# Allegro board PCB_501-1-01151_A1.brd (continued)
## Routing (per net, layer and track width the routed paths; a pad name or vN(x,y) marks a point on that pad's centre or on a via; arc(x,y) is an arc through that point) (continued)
PHYB_RXD0: length 15.5
  TOP w0.142: v1(49.78,30.51) 49.78,31.08 49.66,31.2 49.12,31.2 49,31.33 49,31.5 49.12,31.63 49.83,31.63 49.96,31.75 49.96,31.93 49.83,32.06 49.21,32.06 49.09,32.18 49.09,32.36 49.21,32.48 49.66,32.48 49.78,32.61 49.78,32.88 49.97,33.06 50.26,33.06 50.39,33.18 50.39,33.53 50.51,33.66 50.69,33.66 50.81,33.53 50.81,33.18 50.94,33.06 51.37,33.06 51.54,33.22 51.54,33.9 51.37,34.07 50.36,34.07 50.26,34.17 50.26,34.51 50.43,34.69 50.82,34.69 52.85,36.72 53.53,36.72 U6.C17
  BOTTOM w0.142: R122.2 v1(49.78,30.51)
PHYB_RXD1: length 15.7
  TOP w0.142: U6.C16 v1(54.18,36.57)
  BOTTOM w0.142: v1(54.18,36.57) 54.18,35.21 52.95,33.97 52.74,33.97 52.62,34.1 52.62,35.21 52.49,35.33 52.32,35.33 52.19,35.21 52.19,34.1 52.07,33.97 51.62,33.97 51.49,33.85 51.49,33.33 51.37,33.2 51.19,33.2 51.07,33.33 51.07,34.11 50.94,34.24 50.52,34.24 50.38,34.1 50.38,32.72 50.34,32.68 50.34,31.33 50.23,31.22 49.46,31.22 49.28,31.03 49.28,30.5 R123.2
PHYB_RXER: length 17.5
  TOP w0.142: U6.D16 v1(54.18,37.37)
  BOTTOM w0.142: R125.2 R115.1 51.42,30.84 51.56,30.99 51.56,32.64 52.01,33.09 52.56,33.09 53.22,33.75 53.69,33.75 53.9,33.54 53.9,31.76 54.1,31.56 54.4,31.56 54.58,31.75 54.58,32.63 54.71,32.75 54.99,32.75 55.11,32.88 55.11,33.06 54.99,33.18 54.71,33.18 54.58,33.31 54.58,33.48 54.71,33.61 54.99,33.61 55.11,33.73 55.11,33.91 54.99,34.03 54.71,34.03 54.58,34.16 54.58,34.34 54.71,34.46 54.99,34.46 55.11,34.59 55.11,34.76 54.99,34.89 54.71,34.89 54.58,35.01 54.58,36.97 v1(54.18,37.37)
PHYB_TX_EN: length 5.6
  BOTTOM w0.142: R85.1 44.2,31.98 44.2,28.69 44.72,28.17 U10.49
PHYB_TXD0: length 5.4
  BOTTOM w0.142: U10.48 44.22,28.18 43.56,28.84 R83.1
PHYB_TXD1: length 5.7
  BOTTOM w0.142: R84.1 42.42,29.49 43.72,28.19 U10.47
PMIC_AC_DET: length 6.8
  TOP w0.142: R10.1 R15.2 51.8,61.7 50.5,60.4 48.37,60.4 47.9,59.93 U1.9
PMIC_CC: length 1.2
  TOP w0.142: 40.17,61.73 40.76,61.13 U1.25
PMIC_GPIO1: length 87.4
  TOP w0.142: v1(28.7,44.07) 27.79,44.07 26.6,42.87 26.6,38.23 27.87,36.96 31.5,36.96 32,37.47 R31.2 ; U1.11 48,60.73 48.17,60.9 49.04,60.9 51.05,62.91 R28.1 51.54,65.51 51.68,65.65 51.68,68.46 51.81,68.59 51.81,71.51 49.4,73.91 41.4,73.91 38.8,71.31 34.35,71.31 30.99,67.94 v1(22.99,67.94)
  BOTTOM w0.142: v1(22.99,67.94) 22.99,64.13 25.15,61.98 25.15,56.05 28.07,53.12 28.07,49.53 27.18,48.64 27.18,45.59 v1(28.7,44.07)
PMIC_I2C1_SCL: length 111
  TOP w0.142: U6.G17 53.14,40.18 52.51,39.56 52.51,39 51.76,38.24 51.76,38.23 51.39,37.86 51.39,36.77 47.44,32.82 40.08,32.82 38.35,31.09 30.32,31.09 25.37,36.04 25.37,43.91 26.89,45.43 26.89,47.28 26,48.16 24.61,48.16 23.81,48.96 23.05,48.96 v1(22.73,48.64) ; v1(49.02,56.39) 47.88,57.53 U1.3 ; R580.2 R875.1 16.53,68.6 15.88,67.95 15.88,62.77 16.41,62.23 17.27,62.23 18.16,61.34 18.16,57.79 18.67,57.28 22.99,57.28 v1(23.24,57.53)
  L3_SIG1 w0.142: v1(23.24,57.53) 34,57.53 34.73,56.8 44.9,56.8 45.13,57.02 48.39,57.02 v1(49.02,56.39)
  BOTTOM w0.142: v1(23.24,57.53) 21.46,55.75 21.46,52.2 22.99,50.67 22.99,49.35 22.73,49.09 v1(22.73,48.64)
PMIC_I2C1_SDA: length 99.5
  TOP w0.142: v1(24.33,56.97) 23.82,56.97 23.74,56.9 18.04,56.9 17.72,56.58 17.72,55.57 17.51,55.35 R876.2 R581.2 ; v1(23.62,48.26) 24.06,47.82 25.71,47.82 26.54,46.99 26.54,45.57 25.03,44.06 25.03,35.9 30.18,30.74 38.49,30.74 40.22,32.47 47.58,32.47 47.94,32.82 47.94,32.82 51.73,36.62 51.73,37.71 52.1,38.08 52.1,38.1 52.86,38.86 52.86,39.41 53.18,39.73 54.15,39.73 U6.G16 ; U1.2 47.65,57.13 48.39,56.39 v1(48.39,56.13)
  L3_SIG1 w0.142: v1(48.39,56.13) 47.62,55.37 42.8,55.37 42.16,54.74 39.12,54.74 38.1,55.75 34.04,55.75 32.82,56.97 v1(24.33,56.97)
  BOTTOM w0.142: v1(24.33,56.97) 23.82,56.97 21.81,54.96 21.81,52.34 23.37,50.78 23.37,48.97 23.62,48.71 v1(23.62,48.26)
PMIC_IN_CC#: length 2.6
  TOP w0.142: U1.18 44.27,62.74 v1(44.29,62.76)
  BOTTOM w0.142: v1(44.29,62.76) 43.01,62.76 R766.1
PMIC_INT#: length 85.3
  TOP w0.142: v1(46,53.93) 46,54.42 45.07,55.35 U1.45 ; U6.F5 v1(63.81,38.97)
  L4_SIG2 w0.142: v1(63.81,38.97) 63.41,38.57 52.79,38.57 52.45,38.22 42.74,38.22 42.62,38.1 v1(42.16,38.1) ; v1(25.27,49.78) 29.09,53.61 45.68,53.61 v1(46,53.93)
  BOTTOM w0.142: v1(25.27,49.78) 24.89,49.4 24.89,47.95 25.4,47.45 25.4,40.13 26.8,38.73 26.8,36.18 29.17,33.81 31.26,33.81 31.33,33.74 32.21,33.74 32.27,33.81 33.17,33.81 37.85,38.48 38.86,38.48 41.27,40.89 42.42,40.89 42.93,40.39 R25.1 42.18,38.12 v1(42.16,38.1)
PMIC_PB: length 224.8
  TOP w0.142: U6.J15 v1(54.98,41.37) ; v1(93.22,72.52) 92.2,71.5 92.2,68.83 92.46,68.58 R842.1 ; v1(15.66,51.38) 15.98,51.7 15.98,52.72 15.6,53.11 R841.2
  L3_SIG1 w0.142: v1(54.98,41.37) 52.88,41.37 52.39,41.86 50.99,41.86 50.43,41.31 42.02,41.31 40.57,39.86 40.57,38.81 38.3,36.54 35.91,36.54 33.43,34.06 25.25,34.06 24.77,34.54 12.32,34.54 v1(11.3,33.53) ; v1(15.66,51.38) 15.66,51.84 15.43,52.07 9.94,52.07 7.82,54.2 7.82,73.06 12.54,77.78 21.14,77.78 35.94,92.58 87.38,92.58 93.22,86.74 v1(93.22,72.52)
  BOTTOM w0.142: v1(11.3,33.53) 11.3,34.29 5.62,39.97 5.62,49.05 6.1,49.53 7.87,49.53 8.46,50.12 10.67,50.12 11.25,50.7 12.04,50.7 12.45,50.29 14.57,50.29 v1(15.66,51.38)
PMIC_PB_B: length 75.2
  TOP w0.142: SW2.2 95.17,71.42 94.87,71.12 R20.1 R843.2 R842.2 v1(95.5,68.58) ; v1(46.2,52.92) 45.26,53.86 45.26,54.82 44.83,55.25 44.77,55.25 44.67,55.35 U1.44
  L4_SIG2 w0.142: v1(46.2,52.92) 46.8,52.92 50.12,56.24 51.16,56.24 55.28,60.36 63.97,60.36 64.94,59.39 74.38,59.39 74.94,59.95 75.93,59.95 76.19,59.69 88.75,59.69 90.79,57.66 92.54,57.66 92.86,57.98 93.18,57.98 94.23,59.03 94.23,67.31 v1(95.5,68.58)
PMIC_PFI: length 5.3
  TOP w0.142: U1.16 45.07,62.51 44.94,62.64 44.94,63.42 44.82,63.53 v1(44.82,63.93)
  BOTTOM w0.142: R24.2 R22.1 45.68,64.79 v1(44.82,63.93)
PMIC_PFO#: length 9.5
  TOP w0.142: R859.2 R860.2 51.69,65 51.69,63.12 49.22,60.65 48.27,60.65 47.95,60.33 U1.10
PMIC_PGOOD: length 24.4
  TOP w0.142: R769.1 53.32,60.71 53.47,60.85 v1(53.47,60.96) 53.85,60.96 54.1,60.71 U2.2 55.23,60.71 55.37,60.85 55.37,62.06 55.98,62.67 55.98,63.22 TP40.1 56.77,64.74 57.02,64.99 R23.2
  BOTTOM w0.142: R768.1 44.45,66.93 44.7,67.18 48.35,67.18 48.9,66.63 48.9,64.9 49.66,64.13 53.59,64.13 54.31,63.42 54.31,61.8 v1(53.47,60.96)
PMIC_PWR_EN: length 144.4
  TOP w0.142: U1.46 45.47,55.35 46.52,54.3 46.52,53.91 46.53,53.89 v1(46.53,53.49) ; v1(58.95,71.99) 55.17,71.99 54.61,71.43 54.61,69.98 55.12,69.47 55.12,67.31 54.97,67.16 R88.2 R19.1 ; R859.1 R19.1 ; R19.1 R18.1 ; v1(86.41,77.02) 86.41,77.65 87.88,79.12 95.53,79.12 96.04,78.61 TP34.1 96.77,80.05 94.02,82.8 R833.1 92.19,82.58 U26.1
  L3_SIG1 w0.142: v1(86.41,77.02) 85.07,77.02 84.49,77.6 59.87,77.6 58.29,76.02 58.29,72.64 58.43,72.5 58.44,72.5 v1(58.95,71.99)
  L4_SIG2 w0.142: v1(46.53,53.49) 46.85,53.81 47.12,53.81 49.89,56.58 50.36,56.58 51.01,56.58 55.14,60.71 64.39,60.71 65.36,59.74 73.84,59.74 75.06,60.96 80.77,60.96 81.62,60.11 90,60.11 91.79,58.32 93.03,58.32 93.85,59.14 93.85,71.21 93.05,72.01 91.95,72.01 86.94,77.02 v1(86.41,77.02)
PMIC_PWR_EN_R: length 30.7
  TOP w0.142: R88.1 54.48,68.96 v1(54.61,69.09) ; U6.T9 59.82,47.76 59.82,48.63 59.11,49.33 59.11,54.18 60.66,55.72 61.42,55.72 61.63,55.93 61.63,58.41 60.07,59.97 60.07,62.1 57.69,64.49 57.69,68.55 55.88,70.36 v1(55.09,70.36)
  BOTTOM w0.142: v1(55.09,70.36) 55.09,69.57 v1(54.61,69.09)
PMIC_STBY_REQ: length 1.7
  BOTTOM w0.142: Q41.1 34.69,61.36 34.67,61.34 R765.2
PMIC_WAKE#: length 32.3
  TOP w0.142: U6.R10 v1(58.98,47) ; R26.2 v1(41.91,49.08) 42.29,49.46 42.29,54 43.01,54.71 43.01,55.29 43.07,55.35 U1.40
  L4_SIG2 w0.142: v1(58.98,47) 58.98,49 58.3,49.69 58.3,51.3 56.27,53.33 51.59,53.33 48.76,50.51 43.34,50.51 v1(41.91,49.08)
POR_B: length 142.7
  TOP w0.142: v1(90.17,81.53) 90.17,86.87 91.06,87.76 91.06,89.66 91.95,90.55 93.98,90.55 94.38,90.16 U27.1 ; v1(45.72,79.25) 42.93,79.25 41.02,77.34 41.02,74.8 38.48,72.26 33.66,72.26 29.84,68.45 19.32,68.45 18.56,69.22 15.75,69.22 15.11,68.58 TP35.1 14.38,67.82 14,68.2 D26.2 ; U6.P8 v1(61.41,46.2) ; v1(57.79,57.02) 58.17,57.4 R803.1
  L3_SIG1 w0.142: v1(90.17,81.53) 79.29,81.53 79.19,81.44 68.96,81.44 66.14,78.61 60.34,78.61 59.89,78.16 57.33,78.16 54.74,75.56 v1(52.2,75.56)
  L4_SIG2 w0.142: v1(45.72,79.25) 48.97,79.25 52.2,76.02 v1(52.2,75.56) ; v1(61.41,46.2) 61.81,45.79 63.17,45.79 63.41,46.03 63.41,46.78 63.39,46.8 63.39,47.14 63.41,47.16 63.41,51.29 62.77,51.93 62.77,52.59 58.33,57.02 v1(57.79,57.02)
  BOTTOM w0.142: v1(57.79,57.02) 57.79,57.64 54.65,60.77 54.65,63.57 54.01,64.21 54.01,66.71 54.99,67.69 54.99,68.31 55.63,68.94 55.63,70.61 54.36,71.88 54.36,73.86 52.65,75.56 v1(52.2,75.56)
PRTDIS_M6: length 5.8
  TOP w0.142: U14.53 76.17,67.59 76.96,66.8 76.96,65.79 78.36,64.39 R162.2
PRTDIS_M7: length 4.9
  TOP w0.142: R165.2 78.11,66.68 77.65,67.13 77.65,67.62 76.68,68.59 U14.55
PRTDIS_P6: length 5.8
  TOP w0.142: R161.2 77.72,65.53 77.31,65.95 77.31,67.47 76.69,68.09 U14.54
PRTDIS_P7: length 4.4
  TOP w0.142: R163.2 77.94,67.82 76.72,69.04 75.73,69.04 75.68,69.09 U14.56
PWR_OV_BASE: length 1.4
  TOP w0.381: R4.1 27.11,90.85 Q2.1
PWR_OV_CTL: length 4.5
  TOP w0.142: R4.2 26.42,91.71 26.4,91.69 D1.1 25.93,91.08 25.65,90.81 23.98,90.81 R1.1
PWR_OVP_LED: length 26.3
  TOP w0.142: R8.2 13.59,73.41 13.46,73.53 13.46,76.71 13.97,77.22 v1(13.97,80.01) ; Q2.3 25.1,87.29 v1(23.88,88.52)
  TOP w0.381: Q2.3 26.16,86.49 26.54,86.11 D2.2
  L3_SIG1 w0.142: v1(23.88,88.52) 23.88,87.02 17.7,80.85 14.81,80.85 v1(13.97,80.01)
QSPIA_DATA0: length 16.8
  TOP w0.142: U6.A3 65,33.48 65.14,33.34 66.67,33.34 66.91,33.1 66.91,32.46 67.01,32.35 v1(67.66,32.35)
  BOTTOM w0.142: U9.5 72.82,30.99 72.71,31.1 72.71,31.29 72.59,31.42 71.62,31.42 71.49,31.54 71.49,31.72 71.62,31.84 72.59,31.84 72.71,31.97 72.71,32.26 72.43,32.55 70.2,32.55 TP3.1 69.05,32.35 v1(67.66,32.35)
QSPIA_DATA1: length 16.9
  TOP w0.142: U6.C5 v1(63.81,36.57)
  BOTTOM w0.142: v1(63.81,36.57) 63.81,35.15 63.94,35.02 64.39,35.02 64.52,34.9 64.52,34.72 64.39,34.59 63.94,34.59 63.81,34.47 63.81,34.33 63.94,34.2 65.17,34.2 65.49,33.89 65.49,32.31 66.01,31.79 66.18,31.79 66.52,32.13 66.7,32.13 66.82,32 66.82,31.83 66.48,31.49 66.48,31.31 67.96,29.84 68.08,29.72 68.08,29.41 68.22,29.27 68.75,29.27 68.85,29.17 68.85,28.97 68.73,28.85 68.17,28.85 68.08,28.75 68.08,28.1 68.27,27.92 68.57,27.92 68.72,28.06 68.72,28.39 68.77,28.45 U9.2
QSPIA_DATA2: length 16.7
  TOP w0.142: U6.B5 63.75,35.83 63.75,34.01 63.74,34.01 63.74,32.46 64.02,32.19 64.31,32.19 64.49,32.36 65.15,32.36 65.28,32.24 65.28,31.46 65.4,31.34 65.61,31.34 65.73,31.46 65.73,32.38 65.86,32.51 66.18,32.51 66.31,32.38 66.31,31.77 66.45,31.63 v1(67.44,31.63)
  BOTTOM w0.142: U9.3 68.77,29.72 68.64,29.84 68.64,30.49 68.52,30.62 67.83,30.62 67.71,30.74 67.71,30.92 67.83,31.04 68.51,31.04 68.63,31.17 68.63,31.27 69,31.64 69,31.84 68.9,31.94 67.76,31.94 v1(67.44,31.63)
QSPIA_DATA3: length 21.6
  TOP w0.142: U6.A4 64.2,33.97 64.09,33.86 64.09,32.91 64.31,32.69 64.74,32.69 64.95,32.9 v1(66.43,32.9)
  BOTTOM w0.142: v1(66.43,32.9) 66.93,32.9 68.2,34.17 72.06,34.17 72.4,33.83 73.68,33.83 75.56,31.95 75.75,31.95 77.18,30.53 77.18,29.05 76.76,28.63 76.26,28.63 76.07,28.45 U9.7
QSPIA_SCLK: length 7.4
  BOTTOM w0.142: R809.2 73.04,32.66 73.25,32.45 74.27,32.45 75.22,31.5 75.6,31.5 76.45,30.65 TP4.1 75.56,29.46 75.31,29.72 U9.6
QSPIA_SS0#: length 18
  TOP w0.142: U6.E6 v1(63.01,38.17)
  BOTTOM w0.142: U9.1 R104.1 68.09,27.49 67.65,27.93 67.65,29.54 65.06,32.13 65.06,33.38 64.74,33.7 64.13,33.7 63.97,33.54 63.97,32.62 63.83,32.47 63.57,32.47 63.41,32.63 63.41,37.77 v1(63.01,38.17)
RBIAS: length 3.3
  BOTTOM w0.142: R129.1 37.48,20.96 37.98,21.45 U10.32
RBIAS_HUB: length 1.7
  TOP w0.254: U14.63 75.65,72.59 75.78,72.72 76.12,72.72 R577.2
RES#: length 12.9
  BOTTOM w0.142: R196.2 76.71,9.63 73.55,6.48 69.11,6.48 68.5,5.87 J9.11
RES_LED1: length 1.5
  TOP w0.142: DA6.4 98.14,42.32 98.04,42.42 R205.1
RES_LED2: length 1.7
  TOP w0.142: DA6.3 97.44,42.37 R206.1
RES_LED3: length 1.4
  TOP w0.142: D15.2 R207.1
REV_CHANGE: length 24.8
  TOP w0.142: U6.L14 v1(55.78,43.8)
  L3_SIG1 w0.142: v1(55.78,43.8) 55.39,43.4 53.2,43.4 53.01,43.59 52.42,43.59 51.94,44.07 46.35,44.07 45.34,45.09 42.76,45.09 38.86,41.19 v1(38.86,40.01)
  BOTTOM w0.142: v1(38.86,40.01) 38.35,40.51 R815.2 R814.2
REVRES_1: length 83.4
  TOP w0.142: U6.P11 v1(58.18,46.2) ; R834.1 9.76,50.16 7.49,50.16 v1(6.1,48.77)
  L3_SIG1 w0.142: v1(58.18,46.2) 57.78,45.79 57.22,45.79 56.98,45.56 56.98,44.43 56.75,44.2 55.37,44.2 54.23,45.34 50.55,45.34 49.53,46.35 43.05,46.35 35.85,39.15 33.15,39.15 30.45,36.45 v1(29.72,36.45)
  L4_SIG2 w0.142: v1(29.72,36.45) 28.45,36.45 26.67,34.67 9.27,34.67 5.21,38.73 5.21,48.33 5.64,48.77 v1(6.1,48.77)
  BOTTOM w0.142: R836.1 R839.2 31.64,35.96 31.37,35.69 30.48,35.69 v1(29.72,36.45)
REVRES_2: length 90.5
  TOP w0.142: U6.P10 v1(58.98,46.2) ; R835.1 9.25,49.4 7.62,49.4 6.22,48.01 v1(6.22,47.81)
  L3_SIG1 w0.142: v1(58.98,46.2) 59.38,45.8 59.38,45.23 59.15,45 57.82,45 57.28,44.45 57.28,44.25 56.99,43.96 56.99,42.51 56.26,41.78 52.96,41.78 52.53,42.21 50.84,42.21 50.29,41.65 43.56,41.65 42.93,42.29 41.66,42.29 40.13,40.77 40.13,39.12 37.9,36.89 34.98,36.89 33.22,35.12 32.09,35.12 v1(31.77,34.8)
  L4_SIG2 w0.142: v1(6.22,47.81) 5.58,47.16 5.58,39.13 9.4,35.31 26.54,35.31 28.32,37.08 30.1,37.08 30.74,36.44 30.74,35.83 v1(31.77,34.8)
  BOTTOM w0.142: v1(31.77,34.8) 32.09,35.12 32.88,35.12 33.53,35.77 33.53,37.81 32.22,39.12 R840.2 31.64,39.22 31.23,39.63 31.19,39.63 30.95,39.88 30.22,39.88 30.1,40 R772.1
RTC_XTALI: length 9
  TOP w0.142: U6.T11 v1(58.18,47.8)
  BOTTOM w0.142: X2.1 62.54,51.22 62.24,51.52 61.01,51.52 60.87,51.38 C200.1 59.89,51.38 59.66,51.62 59.05,51.62 58.58,51.15 58.58,48.19 v1(58.18,47.8)
RTC_XTALO: length 9.2
  TOP w0.142: U6.U11 v1(58.18,48.6)
  BOTTOM w0.142: X2.2 62.54,52.51 62.33,52.3 61.05,52.3 60.87,52.49 C201.1 59.88,52.49 59.46,52.06 58.7,52.06 58.18,51.55 v1(58.18,48.6)
RXD0_A: length 4.1
  TOP w0.142: v1(49.02,15.88) 48.9,16 R785.1 R112.1
  BOTTOM w0.142: U10.4 48.72,15.57 v1(49.02,15.88)
RXD0_B: length 2
  BOTTOM w0.142: R122.1 49.27,28.55 49.27,28.01 49.22,27.96 U10.58
RXD1_A: length 4.1
  TOP w0.142: v1(48.22,15.83) 47.15,15.83 46.61,16.38 R117.1
  BOTTOM w0.142: U10.5 v1(48.22,15.83)
RXD1_B: length 1.9
  BOTTOM w0.142: R123.1 48.64,28.87 48.92,28.59 48.92,28.16 48.72,27.95 U10.57
RXER_A: length 2.3
  BOTTOM w0.142: R118.1 49.02,12.7 49.72,13.4 U10.2
RXER_B: length 2
  BOTTOM w0.142: U10.60 50.22,28.35 R125.1
RXLED: length 6
  TOP w0.142: D11.1 v1(9.02,48.77)
  BOTTOM w0.142: v1(9.02,48.77) 9.91,48.77 10.62,48.06 10.62,46.55 11.13,46.04 U20.14
SD1_CD#: length 14.6
  BOTTOM w0.142: J2.CD1 J2.CD2 82.42,23.36 81.91,22.86 81.91,20.08 81.36,19.52 P2.2 80.43,19.52 80.37,19.58 R77.2 R87.1
SD1_CD#_R: length 41.7
  TOP w0.142: U6.J14 v1(55.78,41.37)
  L3_SIG1 w0.142: v1(78.09,19.05) 75.44,19.05 74.46,20.03 74.3,20.03 74.22,20.11 67.2,20.11 66.07,21.24 64.22,21.24 63.8,21.66 63.8,25.88 62.03,27.66 59.34,27.66 58.59,28.41 58.59,38.71 57.78,39.52 57.78,39.94 56.75,40.97 56.19,40.97 v1(55.78,41.37)
  BOTTOM w0.142: v1(78.09,19.05) 78.1,19.04 78.1,18.92 78.25,18.78 R87.2
SD1_CLK: length 47
  TOP w0.142: v1(88.52,32.64) 88.14,32.26 85.77,32.26 84.74,31.23 73.98,31.23 73.84,31.37 73.81,31.37 73.8,31.37 73.36,31.37 73.36,31.38 73.16,31.38 72.84,31.69 72.84,32.26 72.7,32.4 C93.1 72.12,32.38 R81.2
  BOTTOM w0.142: v1(88.52,32.64) 88.52,30.4 88.42,30.3 88.42,29.82 88.9,29.34 88.9,26.54 88.69,26.33 P5.2 88.39,25.03 88.66,24.76 88.66,23.35 89.1,22.91 89.28,22.91 89.55,23.18 89.72,23.18 89.85,23.05 89.85,22.87 89.58,22.61 89.58,22.43 89.85,22.17 89.85,19.93 89.99,19.79 90.35,19.79 90.47,19.91 90.47,23.12 90.6,23.24 90.77,23.24 90.9,23.12 90.9,22.81 91.02,22.69 91.45,22.69 91.57,22.56 91.57,22.39 91.45,22.26 91.02,22.26 90.9,22.14 90.9,21.96 91.02,21.83 91.45,21.83 91.57,21.71 91.57,21.53 91.45,21.41 91.02,21.41 90.9,21.28 90.9,20.83 91.02,20.7 92.46,20.7 92.63,20.87 92.92,20.87 93.05,21 93.05,21.16 93.17,21.29 93.35,21.29 93.48,21.16 93.48,21 93.6,20.87 J2.5
SD1_CLK_R: length 6.4
  TOP w0.142: U6.C1 66.97,36.98 70.04,33.92 70.04,33.17 70.34,32.88 R81.1
SD1_CMD: length 20.7
  BOTTOM w0.142: R82.2 R72.2 87.47,27.7 87.47,26.51 87.29,26.33 P6.2 87,24.38 89.38,22 89.38,19.29 90,18.68 90.29,18.68 90.42,18.8 90.42,18.98 90.54,19.1 90.72,19.1 90.85,18.98 90.85,18.8 90.97,18.68 91.51,18.68 91.63,18.8 91.63,19.46 91.76,19.59 91.93,19.59 92.06,19.46 92.06,18.8 92.18,18.68 92.36,18.68 92.49,18.8 92.49,19.46 92.61,19.59 92.79,19.59 92.91,19.46 92.91,18.8 93.04,18.68 J2.3
SD1_CMD_R: length 30.5
  TOP w0.142: v1(88.01,31.07) 87.56,31.07 87.48,30.99 86.25,30.99 86.07,30.81 82.43,30.81 82.3,30.68 82.3,29.91 82.18,29.79 82,29.79 81.88,29.91 81.88,30.68 81.75,30.81 73.8,30.81 73.66,30.94 73.63,30.94 73.62,30.95 71.54,30.95 71.53,30.94 71.46,30.94 71.02,30.51 70.6,30.51 69.6,31.51 69.6,33.82 66.85,36.56 66.22,36.56 U6.C2
  BOTTOM w0.142: v1(88.01,31.07) 88.01,30.49 87.99,30.47 87.99,29.64 88.14,29.5 R82.1
SD1_DATA0: length 42
  TOP w0.142: U6.B3 65.45,35.73 65.45,34.14 65.72,33.87 66.81,33.87 68.21,32.47 68.21,30.94 70.03,29.12 71.67,29.12 72.11,29.57 73.05,29.57 73.26,29.35 80.22,29.35 82.84,26.73 83.41,26.73 83.53,26.61 83.53,24.92 83.66,24.8 83.84,24.8 83.96,24.92 83.96,26.61 84.09,26.73 84.26,26.73 84.39,26.61 84.39,24.92 84.51,24.8 84.69,24.8 84.81,24.92 84.81,26.61 84.94,26.73 88.65,26.73 89.01,27.1 v1(89.01,30.02)
  BOTTOM w0.142: R107.1 R73.2 89.12,29.95 89.05,30.02 v1(89.01,30.02)
SD1_DATA1: length 43.2
  TOP w0.142: U6.B2 66.17,35.81 66.66,35.81 67.09,35.39 67.16,35.39 68.91,33.64 68.91,31.23 70.32,29.81 71.34,29.81 71.78,30.25 71.82,30.25 71.82,30.26 73.34,30.26 73.34,30.25 73.38,30.25 73.51,30.12 73.64,30.12 73.65,30.11 80.55,30.11 82.19,28.47 85.8,28.47 86.08,28.75 86.08,30.33 86.38,30.63 86.93,30.63 87.01,30.56 89.45,30.56 89.62,30.39 89.62,28.48 89.74,28.36 89.92,28.36 90.04,28.48 90.04,30.39 90.17,30.51 90.35,30.51 90.47,30.39 90.47,28.48 90.6,28.36 90.77,28.36 90.9,28.48 90.9,30.39 91.02,30.51 91.41,30.51 v1(91.95,29.97)
  BOTTOM w0.142: v1(91.95,29.97) 91.5,29.97 91.48,29.95 R74.2 R108.1
SD1_DATA2: length 31.9
  TOP w0.142: v1(82.93,30.14) 85.46,30.14 85.66,29.93 85.66,29.18 85.44,28.96 84.24,28.96 84.11,29.09 84.11,29.45 83.99,29.58 83.81,29.58 83.69,29.45 83.69,29.09 83.56,28.96 83.39,28.96 83.26,29.09 83.26,29.45 83.14,29.58 82.96,29.58 82.83,29.45 82.83,29.09 82.71,28.96 82.3,28.96 80.81,30.46 73.81,30.46 73.81,30.46 73.66,30.46 73.52,30.6 73.48,30.6 73.48,30.6 71.68,30.6 71.68,30.6 71.62,30.6 71.18,30.16 70.46,30.16 69.25,31.37 69.25,33.68 66.74,36.18 U6.B1
  BOTTOM w0.142: v1(82.93,30.14) 83.38,30.14 83.57,29.95 R75.2 R105.1
SD1_DATA3: length 34.8
  TOP w0.142: U6.A2 68.56,32.62 68.56,31.08 70.17,29.47 71.51,29.47 71.94,29.91 71.96,29.91 71.97,29.91 73.19,29.91 73.2,29.91 73.22,29.91 73.36,29.77 80.41,29.77 82.17,28.01 86.32,28.01 86.61,28.3 86.61,28.94 86.74,29.06 87.34,29.06 87.47,28.94 87.47,28 87.59,27.88 87.77,27.88 87.89,28 87.89,28.94 88.02,29.06 88.49,29.06 88.62,29.19 88.62,29.37 88.49,29.49 86.74,29.49 86.61,29.62 v1(86.61,30.1)
  BOTTOM w0.142: v1(86.61,30.1) 86.61,30.1 86.47,29.95 R76.2 R106.1
SD1_VSEL: length 4.3
  TOP w0.142: R35.1 R37.1 90.04,21.08 90.17,21.21 90.17,21.21 90.44,21.48 R33.1 U4.B1
SD2_CLK: length 21.7
  TOP w0.076: 81.03,24.61 80.55,24.13 79.71,24.13 U8.M6
  TOP w0.142: 81.03,24.61 81.5,25.08 81.5,27.47 80.04,28.93 73.49,28.93 72.56,28 71.44,28 71.3,28.14 71.28,28.14 70.82,28.59 69.83,28.59 68.07,30.35 67.58,30.35 R71.2
SD2_CMD: length 25.7
  TOP w0.142: U6.C8 v1(61.41,36.57) ; v1(61.85,24.39) 61.85,20.4 64.54,17.71 66.68,17.71 66.82,17.56 R102.2 R830.1
  BOTTOM w0.142: v1(61.41,36.57) 61.41,36.12 61.76,35.77 61.76,31.96 60.23,30.43 60.23,30.42 60.15,30.34 60.15,26.09 v1(61.85,24.39)
SD2_DATA0: length 29.1
  TOP w0.142: U6.D7 v1(62.21,37.37) ; v1(61.52,25.58) 61.11,25.99 59.59,25.99 59.45,25.85 59.45,25.34 59.76,25.02 60.16,25.02 60.25,25.12 61.03,25.12 61.1,25.04 61.72,25.04 62.25,25.58 63.53,25.58 63.73,25.38 63.73,25.06 63.86,24.93 63.95,24.93 64.08,24.81 64.08,24.63 63.95,24.51 63.86,24.51 63.73,24.38 63.73,23.97 63.74,23.95 63.74,23.78 63.73,23.77 63.73,22.61 64.02,22.31 66.59,22.31 66.69,22.21 R94.2 R822.1
  BOTTOM w0.142: v1(62.21,37.37) 61.81,36.97 61.81,36.1 62.18,35.73 62.18,31.78 60.66,30.26 60.66,30.24 60.61,30.2 60.61,26.49 v1(61.52,25.58)
SD2_DATA1: length 25.7
  TOP w0.142: U6.B7 62.15,35.83 62.15,31.8 62.15,30.63 62.36,30.42 v1(62.36,29.97) ; v1(64.75,24.53) 64.91,24.53 64.92,24.55 66.51,24.55 66.69,24.36 R95.2 R823.1
  BOTTOM w0.142: v1(64.75,24.53) 64.75,24.87 64.67,24.95 64.67,25.03 64.53,25.18 64.12,25.18 63.85,24.91 63.85,23.56 64.65,22.76 64.65,22.56 64.51,22.42 64.31,22.42 63.52,23.21 63.52,25.73 61.98,27.28 61.98,29.09 62.29,29.4 63.18,29.4 63.27,29.5 63.27,30.45 63.16,30.57 62.95,30.57 v1(62.36,29.97)
SD2_DATA2: length 28.7
  TOP w0.142: U6.A7 61.8,35.01 61.72,34.93 61.72,31.01 61.6,30.89 61.18,30.89 61.06,30.76 61.06,30.58 61.18,30.46 61.6,30.46 61.72,30.33 61.72,30.16 61.6,30.03 60.21,30.03 60.09,29.91 60.09,29.73 60.21,29.6 60.62,29.6 60.74,29.48 60.74,28.36 60.87,28.23 61.04,28.23 61.17,28.36 61.17,29.48 61.29,29.6 61.6,29.6 61.72,29.48 61.72,28.97 61.86,28.83 v1(62.48,28.83) ; v1(64.75,25.67) 64.91,25.67 64.92,25.69 66.54,25.69 66.69,25.54 R96.2 R824.1
  BOTTOM w0.142: v1(64.75,25.67) 64.22,25.67 63.86,26.03 63.86,26.29 63.98,26.41 64.55,26.41 64.7,26.56 64.7,26.73 64.57,26.87 62.99,26.87 62.87,26.99 62.87,27.19 62.99,27.32 63.92,27.32 64.04,27.44 64.04,27.62 63.92,27.74 62.58,27.74 62.45,27.87 62.45,28.05 62.58,28.17 63.91,28.17 64.04,28.3 64.04,28.69 63.89,28.83 v1(62.48,28.83)
SD2_DATA3: length 27.1
  TOP w0.142: R825.1 R97.2 66.69,18.94 65.89,18.13 64.8,18.13 63.5,19.43 63.5,19.94 63.62,20.07 63.9,20.07 64.02,20.19 64.02,20.37 63.9,20.49 63.62,20.49 63.5,20.62 63.5,21.06 63.26,21.3 62.56,21.3 62.39,21.47 62.39,24.45 62.44,24.51 v1(62.44,24.97) ; U6.D6 v1(63.01,37.37)
  BOTTOM w0.142: v1(63.01,37.37) 62.61,36.97 62.61,31.6 61.09,30.08 61.09,30.07 61.04,30.02 61.04,26.86 62.44,25.46 v1(62.44,24.97)
SD2_DATA4: length 25.9
  TOP w0.142: U6.C6 v1(63.01,36.57) ; v1(62.87,24.26) 62.87,23.72 62.99,23.6 63.17,23.6 63.3,23.47 63.3,23.3 63.17,23.17 62.99,23.17 62.87,23.05 62.87,21.99 63.13,21.73 63.56,21.73 64.12,21.17 64.45,21.17 64.57,21.05 64.57,19.66 64.7,19.54 64.87,19.54 65,19.66 65,21.05 65.12,21.17 66.59,21.17 66.69,21.06 R98.2 R826.1
  BOTTOM w0.142: v1(63.01,36.57) 63.01,36.12 63.12,36.01 63.12,31.5 61.47,29.84 61.47,27.05 63.09,25.42 63.09,24.49 v1(62.87,24.26)
SD2_DATA5: length 28.7
  TOP w0.142: v1(64.75,23.39) 64.91,23.39 64.92,23.41 66.51,23.41 66.69,23.23 R99.2 R827.1 ; v1(65.28,29.59) 64.86,30.01 64.63,30.01 64.49,30.15 64.48,30.15 63.87,30.75 63.37,30.75 63.02,31.1 63.02,35.76 U6.B6
  BOTTOM w0.142: v1(64.75,23.39) 65.41,23.39 65.63,23.61 65.63,24.6 65.75,24.72 65.95,24.72 66.04,24.63 66.04,23.91 66.18,23.77 66.45,23.77 66.56,23.89 66.56,24.66 66.62,24.72 66.72,24.72 66.84,24.85 66.84,25.02 66.72,25.15 65.75,25.15 65.63,25.27 65.63,25.59 65.75,25.71 67.94,25.71 68.06,25.84 68.06,26.02 67.94,26.14 65.75,26.14 65.63,26.27 65.63,26.44 65.75,26.57 66.46,26.57 66.59,26.69 66.59,26.87 66.46,26.99 65.75,26.99 65.63,27.12 65.63,27.63 65.15,28.11 65.15,29.01 65.28,29.14 v1(65.28,29.59)
SD2_DATA6: length 28.6
  TOP w0.142: U6.A6 62.6,30.89 62.96,30.52 62.96,28.7 63.09,28.58 63.31,28.58 63.43,28.7 63.43,30.06 63.56,30.18 63.83,30.18 63.95,30.06 63.95,29.21 64.08,29.08 v1(64.64,29.08) ; R828.1 R100.2 66.69,26.65 66.51,26.84 65,26.84 64.73,26.57 63.7,26.57 63.58,26.44 63.58,26.15 63.45,26.02 63.28,26.02 63.15,26.15 63.15,26.44 63.03,26.57 62.85,26.57 62.72,26.44 62.72,26.15 62.6,26.02 62.42,26.02 62.3,26.15 62.3,26.44 62.17,26.57 59.64,26.57 59.47,26.73 59.47,27.03 59.64,27.19 64.35,27.19 64.52,27.36 v1(64.52,27.81)
  BOTTOM w0.142: v1(64.52,27.81) 64.52,28.5 64.64,28.63 v1(64.64,29.08)
SD2_DATA7: length 26.1
  TOP w0.142: U6.A5 63.4,31.87 63.56,31.71 64.69,31.71 64.83,31.57 64.83,31.26 65.23,30.86 65.23,30.66 65.01,30.43 64.81,30.43 64.43,30.81 64.43,30.95 64.14,31.25 63.7,31.25 v1(63.69,31.26) ; v1(66.36,28.51) 66.36,28.81 66.22,28.95 65.92,28.95 65.67,28.71 65.67,28.15 65.81,28.01 66.55,28.01 66.69,27.87 R858.2 67.24,26.89 67.58,26.89 67.76,27.07 67.76,27.34 R829.1
  BOTTOM w0.142: v1(63.69,31.26) 63.69,31.9 63.81,32.02 64.07,32.02 64.32,31.78 64.32,31.44 64.94,30.81 64.94,30.64 64.62,30.31 64.44,30.31 64,30.75 63.83,30.75 63.7,30.62 63.7,30.45 64.07,30.08 64.07,29.9 63.78,29.6 63.78,29.43 63.94,29.26 64.12,29.26 65.22,30.36 65.39,30.36 65.79,29.96 65.79,29.61 65.92,29.49 66.38,29.49 66.47,29.39 66.47,29.16 66.38,29.06 65.88,29.06 65.76,28.94 65.76,28.11 66.01,27.85 66.22,27.85 66.36,27.99 v1(66.36,28.51)
SD2_RESET#: length 36.2
  TOP w0.076: U8.K5 78.22,23.63 78.22,23.86 78.16,23.93 77.48,23.93 77.41,24 77.41,24.09 77.48,24.16 78.16,24.16 78.22,24.23 78.22,24.32 78.16,24.39 77.48,24.39 77.41,24.46 77.41,24.55 77.48,24.62 78.16,24.62 78.22,24.68 78.22,28.07
  TOP w0.142: v1(66.95,29.51) 66.39,29.51 66.24,29.67 66.24,30.04 66.46,30.26 66.98,30.26 67.78,29.46 68.28,29.46 68.47,29.27 R101.2 68.47,28.3 68.73,28.04 69.93,28.04 70.06,27.91 70.06,27.48 70.18,27.36 70.38,27.36 70.48,27.46 70.48,27.95 70.57,28.04 70.77,28.04 70.94,27.87 70.94,26.61 71.06,26.49 71.24,26.49 71.36,26.61 71.36,27.43 71.49,27.56 71.67,27.56 71.79,27.43 71.79,26.82 71.92,26.69 72.09,26.69 72.22,26.82 72.22,27.43 72.34,27.56 72.98,27.56 73.74,28.32 74.33,28.32 74.51,28.5 74.76,28.5 74.94,28.32 75.19,28.32 75.37,28.5 75.61,28.5 75.79,28.32 76.04,28.32 76.22,28.5 76.47,28.5 76.65,28.32 76.89,28.32 77.07,28.5 77.32,28.5 77.5,28.32 78.06,28.32 78.22,28.15 78.22,28.07 ; U6.B4 64.65,35.73 64.65,33.68 64.57,33.6 v1(64.57,33.15)
  BOTTOM w0.142: v1(66.95,29.51) 66.95,29.57 64.57,31.95 v1(64.57,33.15)
SD2_STROBE: length 4.3
  TOP w0.076: 76.71,20.96 76.71,21.47 76.87,21.63 77.05,21.63 77.21,21.79 77.21,22.47 77.47,22.73 U8.H5
  TOP w0.142: v1(76.15,20.84) 76.61,20.84 76.71,20.94 76.71,20.96
  BOTTOM w0.142: R103.2 76.48,20.84 v1(76.15,20.84)
SD_VSEL_R: length 53.6
  TOP w0.142: U6.D1 68.25,37.78 68.38,37.65 68.65,37.65 69.08,37.22 69.08,37.01 69.08,36.62 69.66,36.03 69.66,35.98 69.93,35.71 69.93,35.23 71.5,33.66 v1(71.5,33.07) ; R33.2 93.21,20.68 93.64,21.11 96.68,21.11 97.99,22.43 97.99,27.68 92.23,33.45 v1(89.38,33.45)
  L4_SIG2 w0.142: v1(71.5,33.07) 72.39,33.96 74.89,33.96 77.74,31.12 83.02,31.12 83.56,30.58 88.35,30.58 89.18,31.41 89.18,31.82 89.38,32.02 v1(89.38,33.45)
SDCARD_DAT0: length 10.5
  BOTTOM w0.142: J2.7 91.72,23.07 91.51,23.28 91.51,23.59 91.4,23.71 90.07,23.71 89.64,24.13 89.64,26.3 P4.2 90.08,26.33 90.3,26.54 90.3,27.54 R107.2
SDCARD_DAT1: length 8.3
  BOTTOM w0.142: J2.8 94.32,24.17 93.76,24.74 91.22,24.74 91.06,24.9 P3.2 91.48,26.33 91.69,26.54 91.69,27.9 91.42,28.17 R108.2
SDCARD_DAT2: length 19.4
  BOTTOM w0.142: R105.2 84.96,27.67 84.96,26.54 84.75,26.33 P8.2 84.33,26.03 84.54,25.82 85.06,25.82 86.14,24.74 86.14,23.59 87,22.73 87,20.07 90.59,16.47 J2.1
SDCARD_DAT3: length 17.1
  BOTTOM w0.142: R106.2 86.23,27.67 86.23,26.54 86.02,26.33 P7.2 85.72,25.76 86.57,24.92 86.57,24.05 87.42,23.2 87.42,20.34 90.19,17.58 J2.2
ST_HUB_LEDA1#: length 43.2
  TOP w0.142: R150.1 90.17,88.01 89.15,87 89.15,82.3 85.72,78.87 84.58,78.87 83.88,78.17 83.88,73.98 85.09,72.77 85.09,67.82 81.03,63.76 78.19,63.76 76.58,65.37 76.58,65.79 75.77,66.59 U14.51
ST_HUB_LEDA2#: length 53.9
  TOP w0.142: U14.49 75.68,65.59 75.85,65.41 75.85,65.12 78.24,62.73 80.58,62.73 85.44,67.58 85.44,73.06 84.71,73.79 v1(84.71,78.1) ; R151.1 71.25,79.32 71.63,78.94 v1(71.63,78.49)
  L3_SIG1 w0.142: v1(84.71,78.1) 72.01,78.1 v1(71.63,78.49)
ST_HUB_LEDA3#: length 61.1
  TOP w0.142: v1(85.67,77.7) 85.67,77.25 85.6,77.17 85.6,73.39 85.78,73.2 85.78,65.59 82.58,62.38 75.85,62.38 75.18,61.72 74.37,61.72 73.99,62.1 U14.47 ; R153.1 67.82,81.91 v1(69.6,80.14)
  L3_SIG1 w0.142: v1(85.67,77.7) 85.67,78.16 83.6,80.23 82.23,80.23 82.13,80.14 v1(69.6,80.14)
ST_HUB_LEDA4#: length 45.1
  TOP w0.142: R157.1 v1(48.77,88.65) ; U14.33 66.99,64.02 66.85,63.88 v1(66.8,63.88)
  L3_SIG1 w0.142: v1(66.8,63.88) 66.8,70.21 65.79,71.23 v1(65.79,74.29)
  BOTTOM w0.142: v1(48.77,88.65) 49.28,88.14 49.28,86.36 48.86,85.94 48.86,81.55 52.18,78.23 56.26,78.23 59.56,74.93 65.15,74.93 v1(65.79,74.29)
ST_HUB_LEDA5#: length 56.9
  TOP w0.142: v1(66.42,62.74) 66.42,63.19 66.29,63.32 66.29,64.83 65.78,65.35 65.78,65.86 66.01,66.09 U14.31 ; v1(48.51,87.38) 45.21,90.68 39.73,90.68 R158.1
  L3_SIG1 w0.142: v1(66.42,62.74) 66.42,63.59 66.19,63.81 66.19,70.33 64.64,71.88 v1(64.64,74.29)
  BOTTOM w0.142: v1(48.51,87.38) 48.51,81.41 52.07,77.85 56.01,77.85 59.56,74.29 v1(64.64,74.29)
ST_QSPIA_SCLK: length 14.3
  TOP w0.142: U6.D5 v1(63.81,37.37)
  BOTTOM w0.142: R809.1 71.68,33.71 69.14,33.71 69.02,33.59 69.02,33.17 68.89,33.05 68.72,33.05 68.59,33.17 68.59,33.59 68.47,33.71 68.34,33.71 67.1,32.47 66.18,32.47 65.91,32.74 65.91,33.91 64.21,35.61 64.21,36.97 63.81,37.37 v1(63.81,37.37)
ST_SD2_CLK: length 19.2
  TOP w0.142: U6.D8 v1(61.41,37.37) ; v1(59.56,29.08) 60.21,28.44 60.21,28.25 60.67,27.79 63.63,27.79 63.99,28.15 64,28.15 64.2,28.35 64.71,28.35 65.76,29.39 65.76,30.6 R71.1
  BOTTOM w0.142: v1(61.41,37.37) 61.01,36.97 61.01,36.02 61.33,35.7 61.33,32.13 59.56,30.37 v1(59.56,29.08)
STBY_REQ: length 6.9
  TOP w0.142: v1(39.88,60.96) 40.13,60.96 40.36,60.73 U1.26
  BOTTOM w0.142: v1(39.88,60.96) 39.56,61.28 39.56,62.15 39.35,62.36 38.31,62.36 37.97,62.7 R763.1 37.95,63.75 37.47,63.75 37.21,63.5 Q41.3
SYS_BU: length 2.2
  TOP w0.178: C33.1 40.99,61.9 U1.24
SYS_NRST: length 8.6
  TOP w0.142: R874.2 D27.2 95.26,84.45 95.23,84.47 C599.1 94.38,84.47 94.23,84.32 94.23,84 93.92,83.7 D28.2 91.57,83.7 91.17,83.29 R833.2 91.17,82.31 91.19,82.29 U26.3
TOUCH_BUSY: length 42.3
  TOP w0.142: U6.G14 v1(55.78,39.77)
  L3_SIG1 w0.142: v1(44.07,37.16) 44.45,37.53 44.45,37.77 47.14,40.45 50.79,40.45 51.34,41.01 52.03,41.01 52.87,40.17 55.38,40.17 v1(55.78,39.77)
  L4_SIG2 w0.142: v1(53.89,27.95) 53.89,28.4 54.01,28.52 54.01,31.12 52.02,33.11 52.02,33.29 51.48,33.83 50.41,33.83 49.03,35.21 48.99,35.21 48.89,35.31 45.4,35.31 44.07,36.63 v1(44.07,37.16)
  BOTTOM w0.142: v1(53.89,27.95) 54.12,27.95 56.64,25.43 56.64,21.95 57.75,20.85 60.54,20.85 R199.1
TOUCH_CLOCK: length 39.2
  TOP w0.142: U6.E4 v1(64.61,38.17)
  L4_SIG2 w0.142: v1(54.96,24.99) 56.38,26.41 56.61,26.41 57.62,27.42 60.43,27.42 61.05,28.04 61.05,31.29 63.41,33.64 63.41,34.09 63.4,34.09 63.4,36.4 63.41,36.4 63.41,37.53 63.65,37.77 63.97,37.77 64.38,38.17 v1(64.61,38.17)
  BOTTOM w0.142: v1(54.96,24.99) 55.63,24.33 55.63,21.76 57.39,19.99 58.78,19.99 59.67,19.1 62.18,19.1 62.6,18.68 62.6,18.68 63.13,18.15 63.13,18.15 63.33,17.95 63.33,15.78 63.4,15.71 63.56,15.54 63.56,15.08 65.04,13.6 U24.16
TOUCH_CS#: length 32.6
  TOP w0.142: U6.E3 v1(65.41,38.17)
  L4_SIG2 w0.142: v1(65.41,38.17) 65.01,37.77 64.45,37.77 64.21,37.54 64.21,35.81 63.83,35.43 63.83,33.46 61.48,31.11 61.48,27.87 60.6,26.99 57.98,26.99 55.44,24.45 54.67,24.45 54.48,24.64 54.48,25.37 v1(55.01,25.89)
  BOTTOM w0.142: R201.1 59.92,19.68 59.19,20.42 57.57,20.42 56.13,21.86 56.13,24.77 v1(55.01,25.89)
TOUCH_INTR_REQ#: length 64.7
  TOP w0.142: U6.H15 v1(54.98,40.57)
  L3_SIG1 w0.142: v1(42,38.74) 44.07,38.74 46.22,40.88 50.61,40.88 51.16,41.44 52.21,41.44 52.7,40.94 54.61,40.94 v1(54.98,40.57)
  L4_SIG2 w0.142: v1(67.94,17.84) 67.49,17.84 67.44,17.9 63.51,17.9 63.03,18.38 61.57,18.38 61.13,17.94 51.4,17.94 51.25,18.09 50.86,18.09 50.7,17.94 47.25,17.94 43.69,21.5 43.69,23.01 38.81,27.88 38.81,33.79 38.64,33.97 38.64,34.36 38.81,34.54 38.81,36.4 40.64,38.23 41.49,38.23 v1(42,38.74)
  BOTTOM w0.142: v1(67.94,17.84) 67.94,17.29 67.5,16.85 U24.11
TOUCH_MISO: length 44.6
  TOP w0.142: v1(74.04,31.94) 74.04,32.59 69.77,36.86 69.77,37.29 69.77,37.65 69.08,38.34 68.67,38.34 68.48,38.53 67.32,38.53 67.27,38.58 U6.E1
  L4_SIG2 w0.142: v1(69.22,22.35) 68.1,21.24 64.32,21.24 63.51,22.05 63.51,23.34 63.92,23.76 63.92,29.43 64.87,30.38 67.5,30.38 68.15,29.73 71.83,29.73 v1(74.04,31.94)
  BOTTOM w0.142: U24.12 67.46,16.2 68.41,17.15 68.41,17.57 68.42,17.58 68.42,21.56 v1(69.22,22.35)
TOUCH_MOSI: length 45.3
  TOP w0.142: U6.E2 66.25,38.13 68.39,38.13 68.52,38 68.93,38 69.42,37.51 69.42,37.15 69.42,36.7 69.93,36.19 69.93,36.09 73.38,32.65 v1(73.38,31.96)
  L4_SIG2 w0.142: v1(69.22,21.21) 68.82,20.81 64.14,20.81 63.03,21.93 63.03,23.74 63.34,24.06 63.34,29.63 64.52,30.81 67.67,30.81 68.32,30.16 71.58,30.16 v1(73.38,31.96)
  BOTTOM w0.142: v1(69.22,21.21) 68.85,20.84 68.85,18.36 68.85,18.36 68.85,17.4 68.84,17.39 68.84,16.97 67.73,15.87 67.73,15.84 67.53,15.63 67.53,15.22 67.21,14.9 U24.14
TOUCH_X+: length 11.7
  L4_SIG2 w0.142: v1(59.16,10.08) 59.16,10.67 59,10.82 59,11.54 58.65,11.89 58.01,11.89 v1(57.61,12.29)
  BOTTOM w0.142: U24.2 59.19,14.25 58.89,14.54 57.82,14.54 57.51,14.22 57.51,12.4 v1(57.61,12.29) ; v1(59.16,10.08) 58.6,9.52 58.6,9.19 58.4,9 C191.2 R198.1
TOUCH_X-: length 13.9
  L3_SIG1 w0.142: v1(62.28,13.82) 61.46,13 57.42,13 56.95,12.52 56.95,11.95 56.65,11.65 56.63,11.65 v1(56.31,11.33)
  BOTTOM w0.142: R200.1 C192.2 55.73,9 55.96,9.24 55.96,9.25 56.14,9.43 56.14,9.54 56.17,9.57 56.17,10.19 56.25,10.26 56.25,11.27 v1(56.31,11.33) ; U24.4 61.7,15.55 62.28,14.97 v1(62.28,13.82)
TOUCH_XL: length 2.4
  BOTTOM w0.142: R200.2 55.2,6.8 55.2,6.67 55,6.47 J9.38
TOUCH_XR: length 3.4
  BOTTOM w0.142: R198.2 57.49,6.67 56.6,6.67 56,6.06 J9.36
TOUCH_Y+: length 17.7
  TOP w0.142: v1(55.32,11.05) 55.22,10.95 55.22,10 55.68,9.55 59.51,9.55 59.97,9.09 60.79,9.09 60.98,9.28 v1(60.98,12.52)
  BOTTOM w0.142: R202.1 C193.2 54.59,9 55.03,9.44 55.03,10.67 55.32,10.96 v1(55.32,11.05) ; v1(60.98,12.52) 61.77,13.32 61.77,14.71 61.58,14.9 U24.3
TOUCH_Y-: length 14.3
  BOTTOM w0.142: R203.1 C194.2 57.26,9 57.37,9.1 57.37,10.66 57.7,10.99 58.14,10.99 58.39,10.74 59.72,10.74 61.02,12.04 61.18,12.04 61.46,12.32 61.46,12.33 61.82,12.7 62.36,12.7 62.76,13.1 62.76,14.02 62.71,14.07 62.71,15.19 62.55,15.35 61.7,16.2 U24.5
TOUCH_YD: length 2.9
  BOTTOM w0.142: R203.2 56.55,7.22 56.03,6.7 55.9,6.7 55.5,6.3 J9.37
TOUCH_YU: length 2.1
  BOTTOM w0.142: J9.39 54.5,6.59 54.48,6.6 R202.2
TPS2054_OC1#: length 44
  TOP w0.142: v1(86.11,63.37) 86.11,59.18 82.52,55.6 68.99,55.6 63.35,61.23 R816.1 R155.1
  BOTTOM w0.142: U18.16 94.87,64.57 93.24,62.94 86.54,62.94 v1(86.11,63.37)
TPS2054_OC2#: length 45.9
  TOP w0.142: R156.1 62.86,66.17 62.72,66.02 R817.1 61.72,65.17 62.84,64.05 62.84,61.24 68.82,55.26 83.07,55.26 86.74,58.93 v1(86.74,64.13)
  BOTTOM w0.142: v1(86.74,64.13) 87.09,63.78 90.33,63.78 91.06,64.52 U18.13
TPS2054_OC3#: length 51.2
  TOP w0.142: R159.1 R818.1 62.38,69.96 60.4,67.98 60.4,64.86 61.8,63.46 61.8,60.68 68.27,54.22 84.44,54.22 88.26,58.04 88.26,62.74 v1(89.79,64.26)
  BOTTOM w0.142: v1(89.79,64.26) U18.12
TPS2054_OC4#: length 55.2
  TOP w0.142: v1(86.57,55.58) 84.86,53.87 68.12,53.87 61.46,60.54 61.46,63.32 59.94,64.83 59.94,70.49 60.58,71.12 61.47,71.12 62.25,71.9 R819.1 R160.1
  BOTTOM w0.142: U18.9 85.98,64.28 84.96,63.27 84.96,57.19 v1(86.57,55.58)
TXLED: length 4.9
  TOP w0.142: v1(20.71,42.12) 20.79,42.04 D10.1
  BOTTOM w0.142: v1(20.71,42.12) 19.99,42.84 19.8,42.84 19.14,43.5 U20.7
UART1_CTS#: length 8
  TOP w0.142: U6.K15 v1(54.98,43)
  L3_SIG1 w0.142: v1(54.98,43) 53.21,43 52.96,43.24 52.21,43.24 52.21,43.25 51.88,43.25 51.56,43.56 v1(48.51,43.56)
  BOTTOM w0.142: R832.2 v1(48.51,43.56)
UART1_RX_DATA: length 58.1
  TOP w0.142: U6.K16 54.15,42.13 51.24,42.13 46.21,37.1 v1(46.04,37.1)
  BOTTOM w0.142: v1(46.04,37.1) 45.72,36.78 45.72,36.75 44.92,35.94 37.97,35.94 36.5,34.47 35.15,34.47 33.79,33.12 32.56,33.12 32.49,33.05 31.04,33.05 30.97,33.12 27.84,33.12 21.98,38.98 21.98,39.95 22.23,40.2 22.23,44.11 21.43,44.91 21.43,46.64 19.42,48.65 19.42,49.39 19.41,49.4 19.41,49.79 19.42,49.81 19.42,51.43 19.03,51.82 17.92,51.82 17.53,51.42 R167.1 R169.2
UART1_TX_DATA: length 60.4
  TOP w0.142: U6.K14 v1(55.78,43)
  L3_SIG1 w0.142: v1(55.78,43) 55.33,42.55 53.17,42.55 52.82,42.9 52.07,42.9 52.07,42.9 50.45,42.9 50.26,43.08 41.25,43.08 39.44,41.28 39.44,39.4 37.62,37.58 34.66,37.58 33.98,36.9 32.08,36.9 30.14,34.96 28.29,34.96 v1(24.51,38.73)
  BOTTOM w0.142: v1(24.51,38.73) 22.58,40.67 22.58,45.16 22.18,45.55 22.18,46.38 21.04,47.52 21.04,50.07 20.73,50.38 20.73,52.17 20.23,52.67 18.24,52.67 R170.2
USB2ANY_I2C_SCL: length 3.3
  TOP w0.142: H1.9 R875.2
USB2ANY_I2C_SDA: length 3.3
  TOP w0.142: H1.10 R876.1
USB_HOST_DN: length 45.8
  TOP w0.127: U14.58 75.64,70.09 75.76,70.21 76.18,70.21 77.3,69.09 80,69.09 80.12,69.21 80.99,69.21 81.12,69.09 81.12,68.85 80.95,68.69 v1(80.95,68.55) ; U6.T13 v1(56.58,47.8)
  L3_SIG1 w0.127: v1(80.95,68.55) 80.95,68.76 81.15,68.96 81.15,69.1 81.02,69.22 79.38,69.22 79.15,69 79.15,68.84 79.21,68.78 79.21,68.62 79.1,68.51 78.94,68.51 78.88,68.57 78.73,68.57 78.61,68.46 78.61,68.3 78.67,68.24 78.67,68.08 78.56,67.97 78.4,67.97 78.34,68.03 78.19,68.03 75.68,65.52 73.39,65.52 72.63,64.76 69.96,64.76 68.92,63.72 68.92,63.44 69.1,63.27 69.1,63.06 68.92,62.88 68.92,61.05 63.61,55.74 62.62,55.74 61.19,54.3 61.19,53.64 57.7,50.15 57.7,48.37 57.39,48.06 56.85,48.06 v1(56.58,47.8)
USB_HOST_DP: length 45.8
  TOP w0.127: U14.59 75.64,70.59 75.76,70.48 76.29,70.48 77.41,69.35 79.89,69.35 80.01,69.48 81.1,69.48 81.39,69.2 81.39,68.89 81.61,68.66 v1(81.61,68.55) ; U6.U13 v1(56.58,48.6)
  L3_SIG1 w0.127: v1(56.58,48.6) 56.85,48.33 57.28,48.33 57.43,48.48 57.43,50.26 60.92,53.75 60.92,54.42 62.51,56.01 63.5,56.01 68.66,61.16 68.66,63.83 69.85,65.02 72.52,65.02 73.28,65.79 75.56,65.79 79.27,69.49 81.13,69.49 81.42,69.21 81.42,68.89 81.61,68.7 v1(81.61,68.55)
USB_HOST_ID: length 11.2
  TOP w0.142: U6.M17 53.11,44.18 52.9,43.98 49.84,43.98 46.74,40.87 46.74,40.07 45.9,39.24 R770.2
USB_LDO_DECAP: length 4.4
  TOP w0.254: U6.R12 v1(57.38,47)
  BOTTOM w0.142: 57.42,48.95 57.38,48.91 v1(57.38,47)
  BOTTOM w0.381: 57.42,48.95 C98.1 C97.1
USB_OTG1_CHD#: length 1.9
  TOP w0.142: TP33.1 54.1,49.4 54.6,48.91 U6.U16
USB_OTG1_DN: length 83
  TOP w0.127: v1(5.84,33.94) 5.84,34.24 5.64,34.44 5.64,35.59 5.36,35.88 3.2,35.88 2.91,35.59 2.91,35.3 2.65,35.04 FL6.1 ; v1(54.74,51.05) 54.74,50.66 54.94,50.46 54.94,47.84 U6.T15
  L3_SIG1 w0.127: v1(54.74,51.05) 54.43,51.37 54.43,51.79 54.95,52.27 54.95,52.56 54.82,52.69 53.96,52.69 53.51,52.24 53.51,49.32 52.18,47.99 49.67,47.99 47.5,50.16 47.46,50.16 45.91,50.16 45.91,50.16 34.8,50.16 34.64,50.32 34.04,50.93 30.73,50.93 30.09,50.28 22.75,50.28 22.4,49.94 21.06,49.94 20.72,50.28 12.42,50.28 11.91,50.79 7.1,50.79 5.47,49.16 5.47,37.86 5.64,37.7 5.64,34.53 5.84,34.34 v1(5.84,33.94)
USB_OTG1_DP: length 83
  TOP w0.127: v1(55.4,51.05) 55.4,50.66 55.21,50.46 55.21,48.37 U6.U15 ; FL6.4 3.45,35.04 3.18,35.3 3.18,35.48 3.31,35.61 3.59,35.61 3.7,35.5 3.7,35.42 3.81,35.31 3.97,35.31 4.08,35.42 4.08,35.5 4.19,35.61 4.35,35.61 4.46,35.5 4.46,35.42 4.57,35.31 4.73,35.31 4.84,35.42 4.84,35.5 4.95,35.61 5.25,35.61 5.37,35.48 5.37,34.44 5.18,34.24 v1(5.18,33.94)
  L3_SIG1 w0.127: v1(5.18,33.94) 5.18,34.34 5.37,34.53 5.37,35.23 5.26,35.34 5.22,35.34 5.11,35.45 5.11,35.61 5.22,35.72 5.26,35.72 5.37,35.83 5.37,37.59 5.21,37.75 5.21,49.27 6.99,51.05 12.02,51.05 12.53,50.55 20.83,50.55 21.17,50.2 22.29,50.2 22.64,50.55 29.98,50.55 30.62,51.19 34.15,51.19 34.91,50.43 46.02,50.43 47.61,50.43 49.78,48.26 52.07,48.26 53.24,49.43 53.24,52.35 53.85,52.96 54.93,52.96 55.22,52.67 55.22,52.37 55.72,51.82 55.72,51.37 v1(55.4,51.05)
USB_OTG1_FAULT#: length 182.2
  TOP w0.142: U6.L15 v1(54.98,43.8)
  L3_SIG1 w0.142: v1(31.37,92.96) 31.37,91.19 19.4,79.21 12.66,79.21 6.98,73.53 6.98,54.78 3.3,51.1 3.3,49.53 1.35,47.57 1.35,34.34 2.67,33.02 9.16,33.02 11.41,35.27 21.94,35.27 23.5,36.83 23.5,38.86 23.88,39.24 24.85,39.24 28.67,35.42 30.01,35.42 31.83,37.24 33.56,37.24 34.24,37.92 35.81,37.92 36.65,37.92 37.85,39.12 37.85,40.66 42.78,45.59 47.41,45.59 48.59,44.41 52.09,44.41 52.57,43.94 53.01,43.94 53.08,43.86 53.12,43.86 53.18,43.8 v1(54.98,43.8)
  L4_SIG2 w0.142: v1(31.37,92.96) 32.64,94.23 42.29,94.23 47.62,88.9 47.62,82.64 53.29,76.97 v1(53.74,76.97)
  BOTTOM w0.142: U19.3 56.01,71.75 55.24,72.52 55.24,74.55 54.72,75.08 R86.2 54.29,76.5 54.22,76.5 v1(53.74,76.97)
USB_OTG1_ID: length 70
  TOP w0.142: U6.K13 v1(56.58,43) ; J7.4 7.1,22.85 8,23.75 8,27.69 7.37,28.32 6.47,28.32 5.96,28.83 U17.4 U17.7 5.96,30.85 6.1,30.99 v1(6.1,31.5)
  L3_SIG1 w0.142: v1(6.1,31.5) 6.73,32.13 8.76,32.13 11.56,34.92 24.87,34.92 25.29,34.51 30.35,34.51 32.16,36.32 33.91,36.32 34.82,37.23 37.76,37.23 39.79,39.26 39.79,41.13 41.39,42.74 49.72,42.74 49.9,42.55 52.67,42.55 53.06,42.16 56.26,42.16 56.58,42.49 v1(56.58,43)
USB_OTG1_PWREN: length 181.2
  TOP w0.142: U6.M16 54.25,43.83 53.21,43.83 52.93,43.56 49.77,43.56 47.11,40.9 47.11,39.96 45.89,38.73 45.48,38.73 45.47,38.73 42.75,38.73 42.13,39.35 39.86,39.35 37.75,37.24 32.44,37.24 31.13,35.94 v1(28.83,35.94)
  L3_SIG1 w0.142: v1(35.05,93.34) 35.05,92.71 21.08,78.74 12.68,78.74 7.33,73.39 7.33,54.64 3.65,50.96 3.65,49.39 1.69,47.43 1.69,34.48 2.81,33.37 9.02,33.37 11.27,35.62 21.65,35.62 22.99,36.96 22.99,38.84 23.73,39.59 25.18,39.59 v1(28.83,35.94)
  L4_SIG2 w0.142: v1(52.83,76.45) 47.07,82.21 47.07,87.93 41.66,93.34 v1(35.05,93.34)
  BOTTOM w0.142: v1(52.83,76.45) 52.83,76 54.74,74.1 54.74,72.1 56.35,70.49 U19.4 57.33,69.65 56.62,68.94 R164.2 56.62,68.1 57.42,67.3 R166.1
USBDM_FL1: length 12.1
  TOP w0.127: FL1.2 77.07,77.6 77.72,77.6 78.11,77.98 78.11,78.11 78.23,78.24 78.44,78.24 78.56,78.12 U15.5 U15.6 80.45,78.12 80.56,78.24 81.15,78.24 81.8,78.88 81.8,81.42 80.45,82.76 80.45,83.33 J4.2
USBDM_FL2: length 15.6
  TOP w0.127: J4.6 80.45,85.95 80.45,85.66 80.17,85.38 78.87,85.38 78.18,84.69 78.18,82.48 79.23,81.42 80.37,81.42 81.15,80.64 81.15,80.04 80.85,79.74 80.56,79.74 80.45,79.62 U15.9 U15.2 78.58,79.62 78.47,79.74 78.19,79.74 77.83,80.1 77.06,80.1 FL2.2
USBDM_FL3: length 10.1
  TOP w0.127: FL3.2 63.69,80.2 62.78,80.2 62.69,80.11 62.04,80.11 61.9,80.25 U16.5 U16.6 60.02,80.25 59.9,80.13 59.44,80.13 58.81,80.76 58.81,81.17 58.1,81.88 58.1,82.37 58.21,82.48 58.31,82.48 58.42,82.59 58.42,82.75 58.31,82.86 58.21,82.86 58.1,82.97 58.1,83.33 J5.2
USBDM_FL4: length 18.1
  TOP w0.127: FL4.2 63.69,77.69 62.93,77.69 62.74,77.88 62.74,78.36 62.47,78.63 62.02,78.63 61.9,78.75 U16.2 U16.9 60.02,78.75 59.9,78.63 58.66,78.63 55.82,81.46 55.82,82.68 55.99,82.85 56.1,82.85 56.21,82.96 56.21,83.11 56.1,83.23 55.99,83.23 55.82,83.39 55.82,84.78 56.37,85.33 57.77,85.33 58.1,85.66 58.1,85.95 J5.6
USBDM_FL5: length 10.9
  TOP w0.127: FL5.2 48.66,81.77 48.39,82.04 48.39,84.05 48.08,84.37 47.75,84.37 47.62,84.49 47.62,84.63 47.49,84.75 P15.2 46.83,84.75 46.7,84.63 46.7,84.51 46.57,84.38 42.27,84.38 J6.2
USBDN: length 9.2
  TOP w0.127: R172.2 v1(11.72,40.89)
  BOTTOM w0.127: U20.9 14.61,42.86 14.85,42.62 14.85,41.75 C176.1 14.86,41.04 14.86,40.69 14.73,40.56 14.15,40.56 13.94,40.77 13.74,40.77 13.54,40.56 13.08,40.56 12.88,40.77 12.67,40.77 12.47,40.56 12.05,40.56 v1(11.72,40.89)
USBDN1_DM: length 6.2
  TOP w0.127: FL1.1 74.43,77.59 73.64,77.59 73.52,77.46 73.52,76.85 73.64,76.72 74.02,76.72 74.37,76.37 74.37,76.09 74.48,75.98 74.51,75.98 74.63,75.87 74.63,75.71 74.51,75.6 74.48,75.6 74.37,75.49 74.37,75.33 74.48,75.22 74.51,75.22 74.63,75.11 74.63,74.95 74.51,74.84 74.48,74.84 74.37,74.73 74.37,74.36 74.49,74.24 U14.1
USBDN1_DP: length 6.2
  TOP w0.127: FL1.4 74.43,77.86 73.53,77.86 73.25,77.57 73.25,76.74 73.53,76.45 73.91,76.45 74.11,76.26 74.11,74.36 73.99,74.24 U14.2
USBDN2_DM: length 8.9
  TOP w0.127: U14.3 73.49,74.24 73.37,74.36 73.37,74.96 73.48,75.08 73.57,75.08 73.69,75.19 73.69,75.35 73.57,75.46 73.48,75.46 73.37,75.57 73.37,75.85 72.77,76.45 72.77,79.76 73.11,80.1 74.43,80.1 FL2.1
USBDN2_DP: length 9
  TOP w0.127: U14.4 72.99,74.24 73.11,74.36 73.11,75.74 72.5,76.34 72.5,79.87 73,80.37 74.43,80.37 FL2.4
USBDN3_DM: length 10.9
  TOP w0.127: U14.6 71.99,74.24 71.87,74.36 71.87,75.53 72,75.65 72,77.2 70.08,79.12 69.21,79.12 68.13,80.2 66.33,80.2 FL3.1
USBDN3_DP: length 10.8
  TOP w0.127: FL3.4 66.33,79.94 68.02,79.94 69.1,78.85 69.97,78.85 71.73,77.09 71.73,76.78 71.62,76.67 71.54,76.67 71.42,76.56 71.42,76.4 71.54,76.29 71.62,76.29 71.73,76.18 71.73,75.76 71.61,75.64 71.61,74.36 71.49,74.24 U14.7
USBDN4_DM: length 8.6
  TOP w0.127: U14.8 70.99,74.24 70.87,74.36 70.87,76.6 69.48,77.99 67.83,77.99 67.53,77.69 66.33,77.69 FL4.1
USBDN4_DP: length 8.7
  TOP w0.127: FL4.4 66.33,77.43 67.64,77.43 67.94,77.72 69.37,77.72 70.61,76.48 70.61,76.21 70.5,76.09 70.32,76.09 70.21,75.98 70.21,75.82 70.32,75.71 70.5,75.71 70.61,75.6 70.61,74.36 70.49,74.24 U14.9
USBDN5_DM: length 26.3
  TOP w0.127: FL5.1 48.66,78.5 48.39,78.24 48.39,77.21 51.33,74.27 62.72,74.27 63.89,75.45 69.09,75.45 69.37,75.17 69.37,74.36 69.49,74.24 U14.11
USBDN5_DP: length 26.3
  TOP w0.127: FL5.4 47.86,78.5 48.13,78.24 48.13,77.1 51.22,74.01 62.83,74.01 64,75.18 68.98,75.18 69.11,75.06 69.11,74.36 68.99,74.24 U14.12
USBDP: length 9.2
  TOP w0.127: v1(11.72,39.88) 11.59,39.75 R171.2
  BOTTOM w0.127: U20.8 15.24,42.86 15.11,42.74 15.11,41.76 C175.1 15.13,41.05 15.13,40.58 14.84,40.3 12.13,40.3 v1(11.72,39.88)
USBDP_FL1: length 12.1
  TOP w0.127: J4.3 80.19,83.33 80.19,82.65 80.42,82.42 80.42,82.26 80.33,82.16 80.33,82 80.44,81.89 80.6,81.89 80.69,81.99 80.85,81.99 81.53,81.31 81.53,78.99 81.04,78.5 80.56,78.5 80.45,78.62 U15.7 U15.4 78.56,78.62 78.44,78.5 78.12,78.5 77.84,78.22 77.84,78.09 77.61,77.86 77.06,77.86 76.96,77.96 FL1.3
USBDP_FL2: length 15.5
  TOP w0.127: J4.7 80.19,85.95 80.19,85.77 80.06,85.65 78.76,85.65 77.91,84.8 77.91,82.36 78.11,82.16 78.11,82 78.05,81.94 78.05,81.78 78.17,81.67 78.32,81.67 78.38,81.73 78.54,81.73 79.12,81.15 80.26,81.15 80.89,80.53 80.89,80.15 80.74,80 80.56,80 80.45,80.12 U15.10 U15.1 78.58,80.12 78.47,80 78.3,80 77.94,80.37 77.06,80.37 FL2.3
USBDP_FL3: length 10.2
  TOP w0.127: J5.3 57.83,83.33 57.83,81.77 58.55,81.06 58.55,80.65 59.33,79.86 59.9,79.86 60.02,79.75 U16.7 U16.4 61.9,79.75 62,79.84 62.8,79.84 62.89,79.94 63.69,79.94 FL3.3
USBDP_FL4: length 18.1
  TOP w0.127: FL4.3 63.69,77.43 62.82,77.43 62.47,77.77 62.47,78.25 62.36,78.36 62.02,78.36 61.9,78.25 U16.1 U16.10 60.02,78.25 59.9,78.36 58.55,78.36 55.56,81.35 55.56,84.89 56.26,85.6 57.66,85.6 57.83,85.77 57.83,85.95 J5.7
USBDP_FL5: length 10.8
  TOP w0.127: FL5.3 47.86,81.77 48.13,82.04 48.13,82.81 48.02,82.92 47.96,82.92 47.85,83.03 47.85,83.19 47.96,83.3 48.02,83.3 48.13,83.41 48.13,83.94 47.97,84.1 47.75,84.1 47.62,83.97 47.62,83.84 47.49,83.71 P14.2 46.83,83.71 46.7,83.84 46.7,83.97 46.56,84.12 42.27,84.12 J6.3
USR_B0: length 4.1
  TOP w0.142: R872.2 95.12,54.74 95.17,54.79 SW4.2
USR_B1: length 3.9
  TOP w0.142: SW5.2 97,61.01 96.88,61.13 96.24,61.13 R873.2
USR_BT0: length 51.9
  TOP w0.142: U6.F2 66.25,38.93 66.74,38.93 66.8,38.88 68.62,38.88 68.81,38.69 69.22,38.69 70.08,37.83 70.08,37.15 74.55,32.68 74.55,32.13 75.02,31.67 84.57,31.67 85.59,32.69 87.7,32.69 88.6,33.59 88.6,35.56 89.21,36.16 89.38,36.16 90.81,37.59 90.81,52.33 92.22,53.74 C195.1 R204.2 93.85,54.72 R872.1
USR_BT1: length 60.4
  TOP w0.142: R873.1 94.47,61.61 94.49,61.59 R208.2 C196.1 91.46,60.73 90.55,59.82 90.55,53.47 89.53,52.45 v1(89.53,48.64)
  TOP w0.254: U6.F3 v1(65.41,38.97)
  L4_SIG2 w0.142: v1(65.41,38.97) 67.35,38.97 71.51,34.81 75.25,34.81 78.09,31.97 84.73,31.97 85.34,32.59 87.07,32.59 88.77,34.29 88.77,35.73 89.21,36.16 89.66,36.16 89.99,36.49 89.99,48.19 v1(89.53,48.64)
USR_LED1: length 56.8
  TOP w0.142: v1(91.47,43.71) 92.21,44.45 97.3,44.45 R205.2 ; U6.D4 v1(64.61,37.37)
  L4_SIG2 w0.142: v1(64.61,37.37) 65.01,36.97 65.01,35.79 70.22,30.59 71.33,30.59 73.18,32.44 74.26,32.44 77.49,29.22 79.94,29.22 80.75,28.4 91.23,28.4 92.43,29.6 92.43,35.78 91.57,36.64 91.57,41.02 91.95,41.4 91.95,43.23 v1(91.47,43.71)
USR_LED2: length 51.4
  TOP w0.142: U6.D3 v1(65.41,37.37) ; v1(91.28,42.42) 92.57,43.71 R206.2
  L4_SIG2 w0.142: v1(65.41,37.37) 68.59,34.19 68.59,32.71 69.4,31.9 72.03,31.9 73,32.87 74.44,32.87 77.66,29.64 80.34,29.64 81.15,28.83 89.99,28.83 91.86,30.7 91.86,35.46 91,36.33 91,41.68 91.28,41.97 v1(91.28,42.42)
USR_LED3: length 40.1
  TOP w0.142: v1(70.74,33.19) 70.74,33.78 69.47,35.05 69.47,35.79 69.45,35.81 69.45,35.82 68.73,36.53 68.73,36.96 68.48,37.21 68.1,37.21 67.98,37.34 66.24,37.34 U6.D2 ; v1(89.41,35.69) 92.46,35.69 95.14,38.37 R207.2
  L4_SIG2 w0.142: v1(70.74,33.19) 71.94,34.39 75.07,34.39 77.91,31.55 84.9,31.55 85.52,32.16 87.05,32.16 87.3,32.16 89.2,34.07 89.2,35.03 89.41,35.23 v1(89.41,35.69)
VREF_TOUCH_C: length 1.6
  BOTTOM w0.142: C189.2 66.53,19.24 U24.9
WDOG_ANY: length 184.2
  TOP w0.142: U27.2 93.73,90.03 93.58,90.17 92.07,90.17 91.69,89.79 R771.2 94.51,87.27 94.84,87.6 94.84,90.33 93.47,91.69 v1(93.47,93.47) ; U6.M15 54.99,44.59 53.02,44.59 52.76,44.32 49.84,44.32 45.88,40.36 v1(42.04,40.36)
  BOTTOM w0.142: v1(93.47,93.47) 93.47,93.98 92.27,95.19 87.48,95.19 86.94,94.65 86.54,94.65 86,95.19 26.61,95.19 22.07,90.65 22.07,73.08 21.62,72.63 21.62,71.98 22.5,71.1 22.5,63.48 23.34,62.64 23.34,58.68 21.12,56.46 21.12,50.7 21.46,50.36 21.46,47.8 21.41,47.76 22.53,46.65 22.53,45.92 23.11,45.34 23.11,41.4 26.42,38.1 26.42,36.07 29.02,33.46 31.12,33.46 31.18,33.4 32.35,33.4 32.41,33.46 33.46,33.46 37.97,37.97 39.2,37.97 41.58,40.36 v1(42.04,40.36)
X1_ENETPHY: length 3.2
  BOTTOM w0.142: U10.70 52.94,20.95 52.95,20.96 54.23,20.96 54.61,20.57 R132.2
XTALI: length 11.2
  TOP w0.142: U6.T16 54.23,47.75 54.23,48.74 53.82,49.15 53.59,49.15 52.98,49.76 R263.2 52.98,50.91 52.99,50.92 C204.1 52.2,52.48 52.2,54.47 52.38,54.65 X3.3 54.61,54.65 54.63,54.63 R821.2
XTALIN_HUB: length 7.1
  TOP w0.142: U14.61 76.16,71.59 76.78,72.21 R148.1 77.93,72.21 C129.1 78.65,72.07 80.66,72.07 80.96,72.38 X1.1
XTALO: length 7
  TOP w0.142: X3.1 51.1,51.87 C205.1 51.71,51.69 52.18,51.22 R263.1 52.18,49.93 53.32,48.78 53.32,47.86 U6.T17
XTALOUT_HUB: length 8.4
  TOP w0.142: U14.60 76.29,71.09 76.6,71.41 R148.2 77.58,71.41 77.68,71.31 C130.1 78.61,71.7 82.17,71.7 82.51,71.36 X1.3
N20222589: length 1.5
  TOP w0.381: R7.1 26.14,82.91 26.12,82.93 D5.2
